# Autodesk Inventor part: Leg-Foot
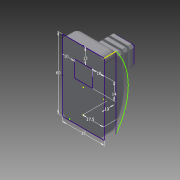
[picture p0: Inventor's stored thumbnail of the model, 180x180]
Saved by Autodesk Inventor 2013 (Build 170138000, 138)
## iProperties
Created: 2013-03
Part Number: Leg-Foot
Material: Generic
Document SubType Name: Modeling
Designer: frankenteddy
Density: 1 g/cm^3
Author: frankenteddy
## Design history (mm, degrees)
sketch "Sketch1"
  geometry: L1 (-17.5, 30)-(17.5, 30); L2 (17.5, 30)-(17.5, -30); L3 (17.5, -30)-(-17.5, -30); L4 (-17.5, -30)-(-17.5, 30); L5 (-7.5, 17)-(7.5, 17); L6 (7.5, 17)-(7.5, 3); L7 (7.5, 3)-(-7.5, 3); L8 (-7.5, 3)-(-7.5, 17); 3 further points
  constraints: 16 end point, 4 parallel, 2 horizontal, 2 midpoint, 2 perpendicular, 1 horizontal alignment, 1 vertical alignment
  dimensions: "d0" = 35 distance of L2.end L3.end; "d1" = 60 distance of L1.end L2.end; "d4" = 13 distance between parallel lines of L5 L1; "d5" = 10 distance between parallel lines of L4 L8; "d6" = 10 distance between parallel lines of L2 L6; "d101" = 14 distance of L7.end L5.start
extrude "Extrusion1" new body sketch "Sketch1" distance "d2" = 10; taper "d3" = 0 deg
extrude "Extrusion2" join sketch "Sketch1" distance "d8" = 35; taper "d9" = 0 deg
sketch "Sketch2"
  geometry: L1 (0, 0)-(0, 10) reference; L2 (0, 10)-(60, 10); L3 (0, 10)-(60, 10) reference; L4 (50, 2.51)-(50, 12.794); A1 r 49.274 centre (30, -29.089) between (60, 10) and (0, 10); 2 further points
  constraints: 4 end point, 2 perpendicular, 2 point on circle, 1 centre point, 1 point on line
extrude "Extrusion3" join sketch "Sketch2" distance "d10" = 35; taper "d11" = 0 deg
fillet "Fillet1" dims "d22" = 5
fillet "Fillet2" dims "d23" = 5
sketch "Sketch3"
  geometry: L1 (-7.5, -17)-(7.5, -17) reference; L2 (7.5, -17)-(7.5, -3) reference; L3 (7.5, -3)-(-7.5, -3) reference; L4 (-7.5, -3)-(-7.5, -17) reference; L5 (-7.5, -3)-(7.5, -3); L6 (7.5, -3)-(7.5, -17); L7 (7.5, -17)-(-7.5, -17); L8 (-7.5, -17)-(-7.5, -3); L9 (0, -3)-(0, -17); 3 further points
  constraints: 10 end point, 3 midpoint, 2 parallel, 1 coincident, 1 horizontal, 1 perpendicular
workplane "Work Plane1"
sketch "Sketch4"
  geometry: L1 (0, 0)-(-12, 0); L2 (-12, 0)-(-12, 14); L3 (-12, 14)-(0, 14); L4 (0, 14)-(0, 0); L5 (0, 7)-(-12, 7); L6 (-7, 7)-(3, 7); A1 r 5 centre (-2, 7) between (-7, 7) and (3, 7); 1 further point
  constraints: 12 end point, 2 midpoint, 2 parallel, 2 point on circle, 2 point on line, 1 centre point, 1 collinear, 1 horizontal, 1 perpendicular
  dimensions: "d25" = 12 distance of L2.end L3.end; "d26" = 14 distance of L1.end L2.end; "d27" = 10 diameter of A1; "d28" = 2 distance from line of L4 A1.centre
revolve "Revolution1" sketch "Sketch4" stored, may be unused: angle "d29" = 90 deg
workplane "Work Plane2"
sketch "Sketch5"
  geometry: L1 (0, 0)-(-17.5, 0) reference; L2 (0, 10)-(-22.031, 10); 2 further points
  constraints: 4 end point, 2 horizontal, 1 parallel, 1 point on line
  dimensions: "d41" = 10 distance between parallel lines of L1 L2; "d42" = 17.5 horizontal distance of L1.start point (-17.5, 10)
workplane "Work Plane6"
sketch "Sketch7"
  geometry: L1 (7.878, 8.949)-(8.504, 13.263); L2 (11.787, 7.02)-(7.878, 8.949); L3 (8.504, 13.263)-(12.801, 14); L4 (12.801, 14)-(14.83, 10.142); L5 (14.83, 10.142)-(11.787, 7.02); L6 (0, 13)-(5.878, 8.729); L7 (5.878, 8.729)-(3.633, 1.82); L8 (3.633, 1.82)-(-3.633, 1.82); L9 (-5.878, 8.729)-(0, 13); L10 (-3.633, 1.82)-(-5.878, 8.729); L11 (-8.765, 13.525)-(-7.878, 9.257); L12 (-7.878, 9.257)-(-11.663, 7.094); L13 (-13.098, 14)-(-8.765, 13.525); L14 (-11.663, 7.094)-(-14.889, 10.026); L15 (-14.889, 10.026)-(-13.098, 14); L16 (0, 20)-(0, -5.822) reference; 5 further points; 1 other entity
  constraints: 32 end point, 1 perpendicular, 1 vertical, 34 other
  dimensions: "d43" = 3 distance from line of point (-11.259, 10.78) L14; "d44" = 3 distance from line of point (11.16, 10.675) L2; "d45" = 5 distance from line of point (0, 6.82) L8; "d47" = 0 distance from line of L16 point (0, 6.82); "d48" = 2 horizontal distance of L9.start L11.end; "d49" = 2 horizontal distance of L1.start L6.end; "d102" = 10 dimension on L6.start; "d105" = 9 dimension on L13.start; "d106" = 9 dimension on L3.end
extrude "Extrusion5" cut sketch "Sketch7" distance "d50" = 3; taper "d51" = 0 deg
sketch "Sketch8"
  geometry: L1 (15, -14.906)-(15, 0) reference; L2 (0, 0)-(15, 0) reference; L3 (0, -14.906)-(0, 0) reference; L4 (0, -2)-(15, -2); L5 (15, -2)-(15, -5); L6 (15, -5)-(0, -5); L7 (0, -5)-(0, -2); L8 (0, -7)-(15, -7); L9 (15, -7)-(15, -10); L10 (15, -10)-(0, -10); L11 (0, -10)-(0, -7); L12 (0, -12)-(15, -12); L13 (15, -12)-(15, -15); L14 (15, -15)-(0, -15); L15 (0, -15)-(0, -12); 1 further point
  constraints: 24 end point, 6 parallel, 6 point on line, 3 horizontal, 3 perpendicular
  dimensions: "d52" = 3 distance of L4.end L5.end; "d53" = 3 distance of L8.end L9.end; "d55" = 2 distance between parallel lines of L4 L2; "d60" = 2 distance between parallel lines of L8 L6; "d107" = 3 distance of L12.end L13.end; "d108" = 2 distance between parallel lines of L12 L10
sketch "Sketch9"
  geometry: L1 (14, -17.84)-(14, 0) reference; L2 (0, 0)-(14, 0) reference; L3 (0, -14.906)-(0, 0) reference; L4 (0, -2)-(14, -2); L5 (14, -2)-(14, -5); L6 (14, -5)-(0, -5); L7 (0, -5)-(0, -2); L8 (0, -7)-(14, -7); L9 (14, -7)-(14, -10); L10 (14, -10)-(0, -10); L11 (0, -10)-(0, -7); L12 (0, -12)-(14, -12); L13 (14, -12)-(14, -15); L14 (14, -15)-(0, -15); L15 (0, -15)-(0, -12); 2 further points
  constraints: 24 end point, 6 parallel, 6 point on line, 3 horizontal, 3 perpendicular
  dimensions: "d56" = 3 distance of L4.end L5.end; "d57" = 3 distance of L8.end L9.end; "d58" = 2 distance between parallel lines of L2 L4; "d59" = 2 distance between parallel lines of L8 L6; "d109" = 3 distance of L12.end L13.end; "d110" = 2 distance between parallel lines of L12 L10
extrude "Extrusion6" join sketch "Sketch8" distance "d61" = 2; taper "d62" = 0 deg
extrude "Extrusion7" join sketch "Sketch9" distance "d63" = 2; taper "d64" = 0 deg
mirror "Mirror1"
workplane "Work Plane7"
mirror "Mirror2"
fillet "Fillet4" dims "d97" = 2
fillet "Fillet5" dims "d98" = 2
fillet "Fillet7" dims "d100" = 2
loft "Loft9" dims "d111" = 0, "d112" = 90 deg, "d113" = 0, "d114" = 90 deg
  node "Edges17"
  node "Edges18"
loft "Loft10" dims "d115" = 0, "d116" = 90 deg, "d117" = 0, "d118" = 90 deg
  node "Edges19"
  node "Edges20"
loft "Loft11" dims "d119" = 0, "d120" = 90 deg, "d121" = 0, "d122" = 90 deg
  node "Edges21"
  node "Edges22"
loft "Loft12" dims "d123" = 0, "d124" = 90 deg, "d125" = 0, "d126" = 90 deg
  node "Edges23"
  node "Edges24"
loft "Loft13" dims "d127" = 0, "d128" = 90 deg, "d129" = 0, "d130" = 90 deg
  node "Edges25"
  node "Edges26"
loft "Loft14" dims "d131" = 0, "d132" = 90 deg, "d133" = 0, "d134" = 90 deg
  node "Edges27"
  node "Edges28"
fillet "Fillet8" dims "d135" = 2
mirror "Mirror3"
body "Solid1"
